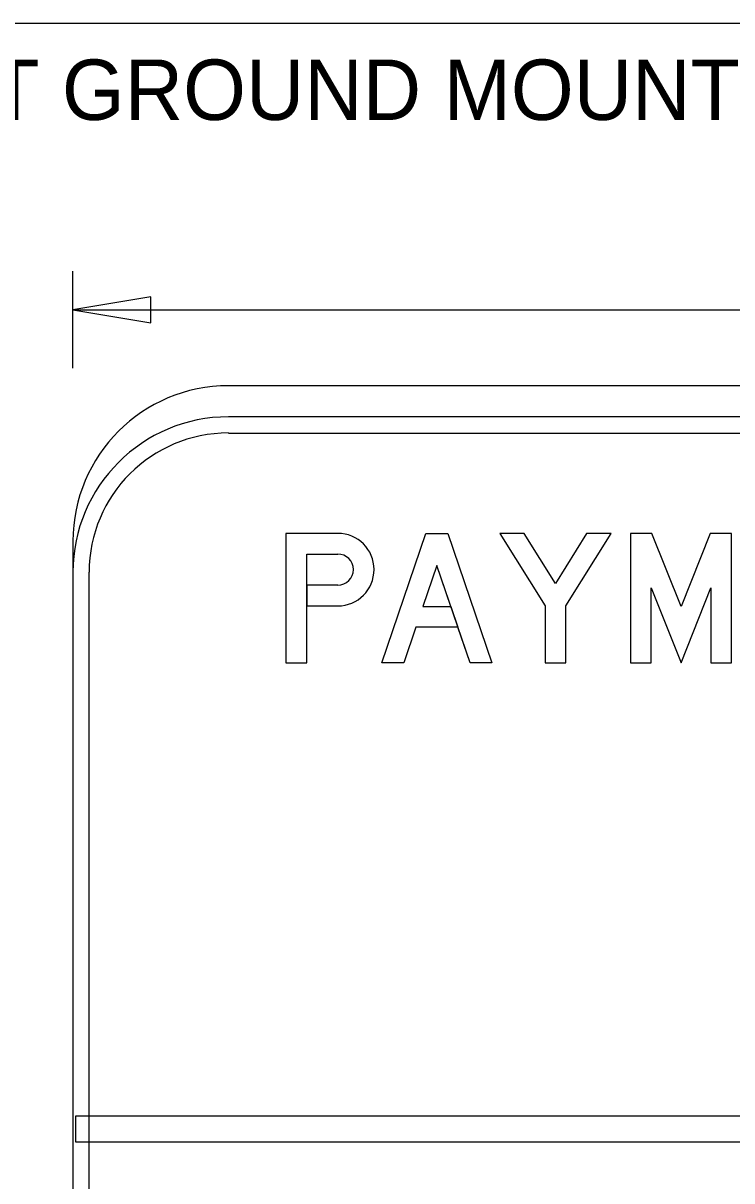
# Model space of a CAD drawing. Extents: x 10268259 to 10268554, y 2141099 to 2141249.
# Drawn here: x 10268353.87 to 10268362.08, y 2141190.12 to 2141203.53 of the extents above; entities that cross this region are included whole.
import ezdxf

# ---------------------------------------------------------------- set-up
doc = ezdxf.new("R2010")
doc.units = 0
for name, color, linetype in [('56', 7, 'Continuous'), ('60', 7, 'Continuous'), ('62', 7, 'Continuous'), ('GSColorFill', 7, 'Continuous'), ('GSDims', 7, 'Continuous'), ('Level 54', 7, 'Continuous')]:
    doc.layers.add(name, color=color, linetype=linetype)

msp = doc.modelspace()

# ---------------------------------------------------------------- linework, layer by layer
at = {"layer": '56'}
for p, q in [((10268357.156, 2141197.378), (10268357.516, 2141197.378)), ((10268357.156, 2141197.378), (10268357.516, 2141197.378)), ((10268357.156, 2141196.778), (10268357.516, 2141196.778)), ((10268381.427, 2141190.868), (10268354.48, 2141190.868)), ((10268354.48, 2141190.868), (10268354.48, 2141190.569)), ((10268381.427, 2141190.868), (10268354.48, 2141190.868)), ((10268354.48, 2141190.868), (10268354.48, 2141190.569)), ((10268381.427, 2141190.868), (10268354.48, 2141190.868)), ((10268354.48, 2141190.868), (10268354.48, 2141190.569)), ((10268354.48, 2141190.569), (10268381.427, 2141190.569)), ((10268354.48, 2141190.569), (10268381.427, 2141190.569)), ((10268354.48, 2141190.569), (10268381.427, 2141190.569))]:
    msp.add_line(p, q, dxfattribs=at)
for points in [[(10268357.516, 2141197.618), (10268356.916, 2141197.618), (10268356.916, 2141196.118), (10268357.156, 2141196.118), (10268357.156, 2141196.778)], [(10268357.516, 2141197.618), (10268356.916, 2141197.618), (10268356.916, 2141196.118), (10268357.156, 2141196.118), (10268357.156, 2141197.378)], [(10268357.516, 2141197.618), (10268356.916, 2141197.618), (10268356.916, 2141196.118), (10268357.156, 2141196.118), (10268357.156, 2141197.378)], [(10268357.516, 2141197.018), (10268357.156, 2141197.018), (10268357.156, 2141197.378), (10268357.516, 2141197.378)], [(10268357.516, 2141197.018), (10268357.156, 2141197.018), (10268357.156, 2141196.778), (10268357.516, 2141196.778)], [(10268357.516, 2141197.018), (10268357.156, 2141197.018), (10268357.156, 2141196.778), (10268357.516, 2141196.778)]]:
    msp.add_lwpolyline(points, dxfattribs=at)
for points in [[(10268358.42, 2141196.53), (10268358.28, 2141196.118), (10268358.026, 2141196.118), (10268358.536, 2141197.618), (10268358.791, 2141197.618), (10268359.301, 2141196.118), (10268359.048, 2141196.118), (10268358.908, 2141196.53)], [(10268358.026, 2141196.118), (10268358.536, 2141197.618), (10268358.791, 2141197.618), (10268359.301, 2141196.118), (10268359.048, 2141196.118), (10268358.664, 2141197.247), (10268358.502, 2141196.77), (10268358.826, 2141196.77), (10268358.908, 2141196.53), (10268358.42, 2141196.53), (10268358.28, 2141196.118)], [(10268358.026, 2141196.118), (10268358.536, 2141197.618), (10268358.791, 2141197.618), (10268359.301, 2141196.118), (10268359.048, 2141196.118), (10268358.664, 2141197.247), (10268358.502, 2141196.77), (10268358.826, 2141196.77), (10268358.908, 2141196.53), (10268358.42, 2141196.53), (10268358.28, 2141196.118)], [(10268359.916, 2141196.118), (10268360.156, 2141196.118), (10268360.156, 2141196.778), (10268360.681, 2141197.618), (10268360.398, 2141197.618), (10268360.036, 2141197.039), (10268359.674, 2141197.618), (10268359.391, 2141197.618), (10268359.916, 2141196.778)], [(10268359.916, 2141196.118), (10268360.156, 2141196.118), (10268360.156, 2141196.778), (10268360.681, 2141197.618), (10268360.398, 2141197.618), (10268360.036, 2141197.039), (10268359.674, 2141197.618), (10268359.391, 2141197.618), (10268359.916, 2141196.778)], [(10268359.916, 2141196.118), (10268360.156, 2141196.118), (10268360.156, 2141196.778), (10268360.681, 2141197.618), (10268360.398, 2141197.618), (10268360.036, 2141197.039), (10268359.674, 2141197.618), (10268359.391, 2141197.618), (10268359.916, 2141196.778)], [(10268362.076, 2141196.118), (10268362.076, 2141197.618), (10268361.828, 2141197.618), (10268361.491, 2141196.769), (10268361.155, 2141197.618), (10268360.906, 2141197.618), (10268360.906, 2141196.118), (10268361.146, 2141196.118), (10268361.146, 2141196.988), (10268361.491, 2141196.118), (10268361.836, 2141196.988), (10268361.836, 2141196.118)], [(10268362.076, 2141196.118), (10268362.076, 2141197.618), (10268361.828, 2141197.618), (10268361.491, 2141196.769), (10268361.155, 2141197.618), (10268360.906, 2141197.618), (10268360.906, 2141196.118), (10268361.146, 2141196.118), (10268361.146, 2141196.988), (10268361.491, 2141196.118), (10268361.836, 2141196.988), (10268361.836, 2141196.118)], [(10268362.076, 2141196.118), (10268362.076, 2141197.618), (10268361.828, 2141197.618), (10268361.491, 2141196.769), (10268361.155, 2141197.618), (10268360.906, 2141197.618), (10268360.906, 2141196.118), (10268361.146, 2141196.118), (10268361.146, 2141196.988), (10268361.491, 2141196.118), (10268361.836, 2141196.988), (10268361.836, 2141196.118)], [(10268358.502, 2141196.77), (10268358.826, 2141196.77), (10268358.664, 2141197.247)]]:
    msp.add_lwpolyline(points, close=True, dxfattribs=at)
for major_axis in [(0, 0.42), (0, 0.42), (0, 0.42), (0, 0.18), (0, 0.18), (0, 0.18)]:
    msp.add_ellipse((10268357.516, 2141197.198), major_axis=major_axis, ratio=0.999993, start_param=3.141593, end_param=6.283185, dxfattribs=at)
at = {"layer": '60'}
msp.add_line((10268341.73, 2141203.528), (10268393.98, 2141203.528), dxfattribs=at)
at = {"layer": 'GSColorFill'}
for p, q in [((10268379.649, 2141199.328), (10268356.249, 2141199.328)), ((10268354.449, 2141197.528), (10268354.449, 2141179.528))]:
    msp.add_line(p, q, dxfattribs=at)
msp.add_arc((10268356.249, 2141197.528), 1.8, 90, 180, dxfattribs=at)
at = {"layer": 'GSDims'}
for p, q in [((10268354.449, 2141199.532), (10268354.449, 2141200.657)), ((10268354.449, 2141200.207), (10268381.261, 2141200.207))]:
    msp.add_line(p, q, dxfattribs=at)
msp.add_lwpolyline([(10268354.449, 2141200.207), (10268355.349, 2141200.057), (10268355.349, 2141200.357)], close=True, dxfattribs=at)
at = {"layer": 'Level 54'}
for p, q in [((10268379.649, 2141198.968), (10268356.249, 2141198.968)), ((10268356.249, 2141198.78), (10268379.649, 2141198.78)), ((10268354.449, 2141197.168), (10268354.449, 2141179.167)), ((10268354.636, 2141179.167), (10268354.636, 2141197.168))]:
    msp.add_line(p, q, dxfattribs=at)
for radius in [1.8, 1.613]:
    msp.add_arc((10268356.249, 2141197.168), radius, 90, 180, dxfattribs=at)

# ---------------------------------------------------------------- texts
at = {"layer": '62'}
msp.add_text('MOUNTING:  MULTI-POST GROUND MOUNT (GM-X)', height=0.7, dxfattribs=at).set_placement((10268342.516, 2141202.407))

doc.saveas('drawing.dxf')
